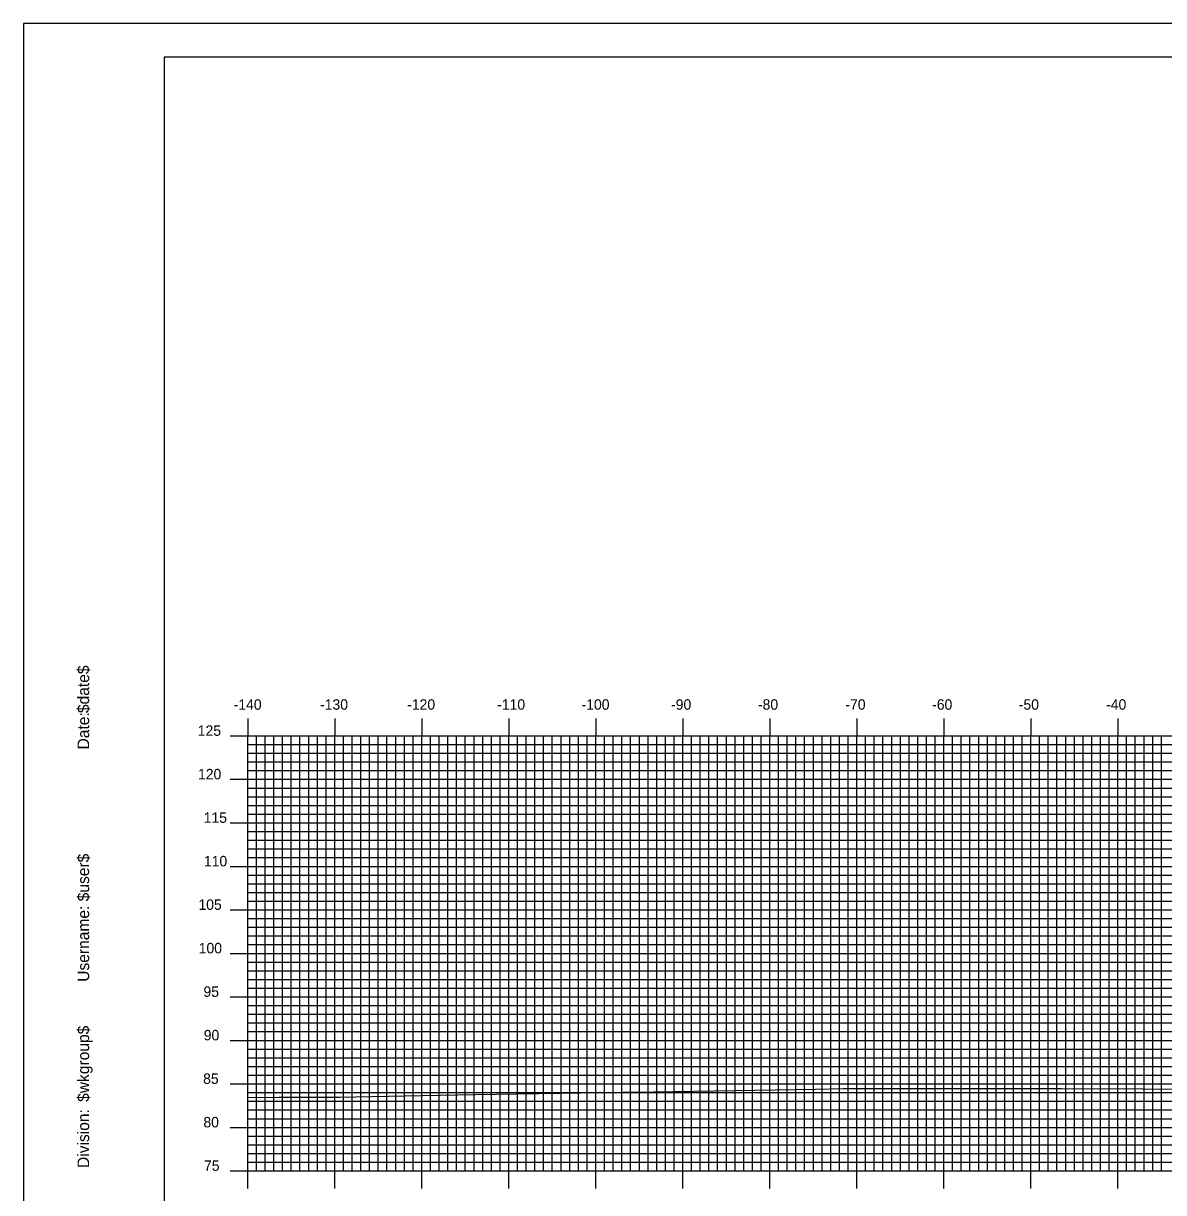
# Model space of a CAD drawing. Extents: x -302 to 42, y -1658 to -1438.
# Drawn here: x -301.7 to -170.6, y -1572.1 to -1437.7 of the extents above; entities that cross this region are included whole.
import ezdxf

# ---------------------------------------------------------------- set-up
doc = ezdxf.new("R2010")
doc.units = 0
for name, color, linetype in [('BORDER', 7, 'Continuous'), ('H_V ANNOTATION', 7, 'Continuous'), ('MAJOR', 7, 'Continuous'), ('MINOR', 7, 'Continuous'), ('PLOT BOUNDARY', 7, 'Continuous'), ('S_Roadway_Centerline', 7, 'Continuous')]:
    doc.layers.add(name, color=color, linetype=linetype)

msp = doc.modelspace()

# ---------------------------------------------------------------- linework, layer by layer
at = {"layer": 'BORDER'}
msp.add_lwpolyline([(-285.49, -1651.6), (34.51, -1651.6), (34.51, -1441.6), (-285.49, -1441.6)], close=True, dxfattribs=at)
at = {"layer": 'MAJOR'}
for p, q in [((-275.89, -1517.6), (-275.89, -1519.6)), ((-265.89, -1517.6), (-265.89, -1519.6)), ((-255.89, -1517.6), (-255.89, -1519.6)), ((-245.89, -1517.6), (-245.89, -1519.6)), ((-235.89, -1517.6), (-235.89, -1519.6)), ((-225.89, -1517.6), (-225.89, -1519.6)), ((-215.89, -1517.6), (-215.89, -1519.6)), ((-205.89, -1517.6), (-205.89, -1519.6)), ((-195.89, -1517.6), (-195.89, -1519.6)), ((-185.89, -1517.6), (-185.89, -1519.6)), ((-175.89, -1517.6), (-175.89, -1519.6)), ((-277.9, -1519.6), (-275.89, -1519.6)), ((-275.89, -1519.6), (4.11, -1519.6)), ((-275.89, -1569.6), (-275.89, -1519.6)), ((-275.89, -1569.6), (-275.89, -1519.6)), ((-275.89, -1519.6), (4.11, -1519.6)), ((-265.89, -1569.6), (-265.89, -1519.6)), ((-255.89, -1569.6), (-255.89, -1519.6)), ((-245.89, -1569.6), (-245.89, -1519.6)), ((-235.89, -1569.6), (-235.89, -1519.6)), ((-225.89, -1569.6), (-225.89, -1519.6)), ((-215.89, -1569.6), (-215.89, -1519.6)), ((-205.89, -1569.6), (-205.89, -1519.6)), ((-195.89, -1569.6), (-195.89, -1519.6)), ((-185.89, -1569.6), (-185.89, -1519.6)), ((-175.89, -1569.6), (-175.89, -1519.6)), ((-277.9, -1524.6), (-275.89, -1524.6)), ((-275.89, -1524.6), (4.11, -1524.6)), ((-277.9, -1529.6), (-275.89, -1529.6)), ((-275.89, -1529.6), (4.11, -1529.6)), ((-277.9, -1534.6), (-275.89, -1534.6)), ((-275.89, -1534.6), (4.11, -1534.6)), ((-277.9, -1539.6), (-275.89, -1539.6)), ((-275.89, -1539.6), (4.11, -1539.6)), ((-277.9, -1544.6), (-275.89, -1544.6)), ((-275.89, -1544.6), (4.11, -1544.6)), ((-277.9, -1549.6), (-275.89, -1549.6)), ((-275.89, -1549.6), (4.11, -1549.6)), ((-277.9, -1554.6), (-275.89, -1554.6)), ((-275.89, -1554.6), (4.11, -1554.6)), ((-277.9, -1559.6), (-275.89, -1559.6)), ((-275.89, -1559.6), (4.11, -1559.6)), ((-277.9, -1564.6), (-275.89, -1564.6)), ((-275.89, -1564.6), (4.11, -1564.6)), ((-277.9, -1569.6), (-275.89, -1569.6)), ((-275.89, -1569.6), (4.11, -1569.6)), ((-275.89, -1569.6), (4.11, -1569.6)), ((-275.89, -1571.61), (-275.89, -1569.6)), ((-265.89, -1571.61), (-265.89, -1569.6)), ((-255.89, -1571.61), (-255.89, -1569.6)), ((-245.89, -1571.61), (-245.89, -1569.6)), ((-235.89, -1571.61), (-235.89, -1569.6)), ((-225.89, -1571.61), (-225.89, -1569.6)), ((-215.89, -1571.61), (-215.89, -1569.6)), ((-205.89, -1571.61), (-205.89, -1569.6)), ((-195.89, -1571.61), (-195.89, -1569.6)), ((-185.89, -1571.61), (-185.89, -1569.6)), ((-175.89, -1571.61), (-175.89, -1569.6))]:
    msp.add_line(p, q, dxfattribs=at)
at = {"layer": 'MINOR'}
for p, q in [((-274.89, -1569.6), (-274.89, -1519.6)), ((-273.89, -1569.6), (-273.89, -1519.6)), ((-272.89, -1569.6), (-272.89, -1519.6)), ((-271.89, -1569.6), (-271.89, -1519.6)), ((-270.89, -1569.6), (-270.89, -1519.6)), ((-269.89, -1569.6), (-269.89, -1519.6)), ((-268.89, -1569.6), (-268.89, -1519.6)), ((-267.89, -1569.6), (-267.89, -1519.6)), ((-266.89, -1569.6), (-266.89, -1519.6)), ((-264.89, -1569.6), (-264.89, -1519.6)), ((-263.89, -1569.6), (-263.89, -1519.6)), ((-262.89, -1569.6), (-262.89, -1519.6)), ((-261.89, -1569.6), (-261.89, -1519.6)), ((-260.89, -1569.6), (-260.89, -1519.6)), ((-259.89, -1569.6), (-259.89, -1519.6)), ((-258.89, -1569.6), (-258.89, -1519.6)), ((-257.89, -1569.6), (-257.89, -1519.6)), ((-256.89, -1569.6), (-256.89, -1519.6)), ((-254.89, -1569.6), (-254.89, -1519.6)), ((-253.89, -1569.6), (-253.89, -1519.6)), ((-252.89, -1569.6), (-252.89, -1519.6)), ((-251.89, -1569.6), (-251.89, -1519.6)), ((-250.89, -1569.6), (-250.89, -1519.6)), ((-249.89, -1569.6), (-249.89, -1519.6)), ((-248.89, -1569.6), (-248.89, -1519.6)), ((-247.89, -1569.6), (-247.89, -1519.6)), ((-246.89, -1569.6), (-246.89, -1519.6)), ((-244.89, -1569.6), (-244.89, -1519.6)), ((-243.89, -1569.6), (-243.89, -1519.6)), ((-242.89, -1569.6), (-242.89, -1519.6)), ((-241.89, -1569.6), (-241.89, -1519.6)), ((-240.89, -1569.6), (-240.89, -1519.6)), ((-239.89, -1569.6), (-239.89, -1519.6)), ((-238.89, -1569.6), (-238.89, -1519.6)), ((-237.89, -1569.6), (-237.89, -1519.6)), ((-236.89, -1569.6), (-236.89, -1519.6)), ((-234.89, -1569.6), (-234.89, -1519.6)), ((-233.89, -1569.6), (-233.89, -1519.6)), ((-232.89, -1569.6), (-232.89, -1519.6)), ((-231.89, -1569.6), (-231.89, -1519.6)), ((-230.89, -1569.6), (-230.89, -1519.6)), ((-229.89, -1569.6), (-229.89, -1519.6)), ((-228.89, -1569.6), (-228.89, -1519.6)), ((-227.89, -1569.6), (-227.89, -1519.6)), ((-226.89, -1569.6), (-226.89, -1519.6)), ((-224.89, -1569.6), (-224.89, -1519.6)), ((-223.89, -1569.6), (-223.89, -1519.6)), ((-222.89, -1569.6), (-222.89, -1519.6)), ((-221.89, -1569.6), (-221.89, -1519.6)), ((-220.89, -1569.6), (-220.89, -1519.6)), ((-219.89, -1569.6), (-219.89, -1519.6)), ((-218.89, -1569.6), (-218.89, -1519.6)), ((-217.89, -1569.6), (-217.89, -1519.6)), ((-216.89, -1569.6), (-216.89, -1519.6)), ((-214.89, -1569.6), (-214.89, -1519.6)), ((-213.89, -1569.6), (-213.89, -1519.6)), ((-212.89, -1569.6), (-212.89, -1519.6)), ((-211.89, -1569.6), (-211.89, -1519.6)), ((-210.89, -1569.6), (-210.89, -1519.6)), ((-209.89, -1569.6), (-209.89, -1519.6)), ((-208.89, -1569.6), (-208.89, -1519.6)), ((-207.89, -1569.6), (-207.89, -1519.6)), ((-206.89, -1569.6), (-206.89, -1519.6)), ((-204.89, -1569.6), (-204.89, -1519.6)), ((-203.89, -1569.6), (-203.89, -1519.6)), ((-202.89, -1569.6), (-202.89, -1519.6)), ((-201.89, -1569.6), (-201.89, -1519.6)), ((-200.89, -1569.6), (-200.89, -1519.6)), ((-199.89, -1569.6), (-199.89, -1519.6)), ((-198.89, -1569.6), (-198.89, -1519.6)), ((-197.89, -1569.6), (-197.89, -1519.6)), ((-196.89, -1569.6), (-196.89, -1519.6)), ((-194.89, -1569.6), (-194.89, -1519.6)), ((-193.89, -1569.6), (-193.89, -1519.6)), ((-192.89, -1569.6), (-192.89, -1519.6)), ((-191.89, -1569.6), (-191.89, -1519.6)), ((-190.89, -1569.6), (-190.89, -1519.6)), ((-189.89, -1569.6), (-189.89, -1519.6)), ((-188.89, -1569.6), (-188.89, -1519.6)), ((-187.89, -1569.6), (-187.89, -1519.6)), ((-186.89, -1569.6), (-186.89, -1519.6)), ((-184.89, -1569.6), (-184.89, -1519.6)), ((-183.89, -1569.6), (-183.89, -1519.6)), ((-182.89, -1569.6), (-182.89, -1519.6)), ((-181.89, -1569.6), (-181.89, -1519.6)), ((-180.89, -1569.6), (-180.89, -1519.6)), ((-179.89, -1569.6), (-179.89, -1519.6)), ((-178.89, -1569.6), (-178.89, -1519.6)), ((-177.89, -1569.6), (-177.89, -1519.6)), ((-176.89, -1569.6), (-176.89, -1519.6)), ((-174.89, -1569.6), (-174.89, -1519.6)), ((-173.89, -1569.6), (-173.89, -1519.6)), ((-172.89, -1569.6), (-172.89, -1519.6)), ((-171.89, -1569.6), (-171.89, -1519.6)), ((-170.89, -1569.6), (-170.89, -1519.6)), ((-275.89, -1520.6), (4.11, -1520.6)), ((-275.89, -1520.6), (-273.89, -1520.6)), ((-275.89, -1521.6), (4.11, -1521.6)), ((-275.89, -1521.6), (-273.89, -1521.6)), ((-275.89, -1522.6), (4.11, -1522.6)), ((-275.89, -1522.6), (-273.89, -1522.6)), ((-275.89, -1523.6), (4.11, -1523.6)), ((-275.89, -1523.6), (-273.89, -1523.6)), ((-275.89, -1525.6), (4.11, -1525.6)), ((-275.89, -1525.6), (-273.89, -1525.6)), ((-275.89, -1526.6), (4.11, -1526.6)), ((-275.89, -1526.6), (-273.89, -1526.6)), ((-275.89, -1527.6), (4.11, -1527.6)), ((-275.89, -1527.6), (-273.89, -1527.6)), ((-275.89, -1528.6), (4.11, -1528.6)), ((-275.89, -1528.6), (-273.89, -1528.6)), ((-275.89, -1530.6), (4.11, -1530.6)), ((-275.89, -1530.6), (-273.89, -1530.6)), ((-275.89, -1531.6), (4.11, -1531.6)), ((-275.89, -1531.6), (-273.89, -1531.6)), ((-275.89, -1532.6), (4.11, -1532.6)), ((-275.89, -1532.6), (-273.89, -1532.6)), ((-275.89, -1533.6), (4.11, -1533.6)), ((-275.89, -1533.6), (-273.89, -1533.6)), ((-275.89, -1535.6), (4.11, -1535.6)), ((-275.89, -1535.6), (-273.89, -1535.6)), ((-275.89, -1536.6), (4.11, -1536.6)), ((-275.89, -1536.6), (-273.89, -1536.6)), ((-275.89, -1537.6), (4.11, -1537.6)), ((-275.89, -1537.6), (-273.89, -1537.6)), ((-275.89, -1538.6), (4.11, -1538.6)), ((-275.89, -1538.6), (-273.89, -1538.6)), ((-275.89, -1540.6), (4.11, -1540.6)), ((-275.89, -1540.6), (-273.89, -1540.6)), ((-275.89, -1541.6), (4.11, -1541.6)), ((-275.89, -1541.6), (-273.89, -1541.6)), ((-275.89, -1542.6), (4.11, -1542.6)), ((-275.89, -1542.6), (-273.89, -1542.6)), ((-275.89, -1543.6), (4.11, -1543.6)), ((-275.89, -1543.6), (-273.89, -1543.6)), ((-275.89, -1545.6), (4.11, -1545.6)), ((-275.89, -1545.6), (-273.89, -1545.6)), ((-275.89, -1546.6), (4.11, -1546.6)), ((-275.89, -1546.6), (-273.89, -1546.6)), ((-275.89, -1547.6), (4.11, -1547.6)), ((-275.89, -1547.6), (-273.89, -1547.6)), ((-275.89, -1548.6), (4.11, -1548.6)), ((-275.89, -1548.6), (-273.89, -1548.6)), ((-275.89, -1550.6), (4.11, -1550.6)), ((-275.89, -1550.6), (-273.89, -1550.6)), ((-275.89, -1551.6), (4.11, -1551.6)), ((-275.89, -1551.6), (-273.89, -1551.6)), ((-275.89, -1552.6), (4.11, -1552.6)), ((-275.89, -1552.6), (-273.89, -1552.6)), ((-275.89, -1553.6), (4.11, -1553.6)), ((-275.89, -1553.6), (-273.89, -1553.6)), ((-275.89, -1555.6), (4.11, -1555.6)), ((-275.89, -1555.6), (-273.89, -1555.6)), ((-275.89, -1556.6), (4.11, -1556.6)), ((-275.89, -1556.6), (-273.89, -1556.6)), ((-275.89, -1557.6), (4.11, -1557.6)), ((-275.89, -1557.6), (-273.89, -1557.6)), ((-275.89, -1558.6), (4.11, -1558.6)), ((-275.89, -1558.6), (-273.89, -1558.6)), ((-275.89, -1560.6), (4.11, -1560.6)), ((-275.89, -1560.6), (-273.89, -1560.6)), ((-275.89, -1561.6), (4.11, -1561.6)), ((-275.89, -1561.6), (-273.89, -1561.6)), ((-275.89, -1562.6), (4.11, -1562.6)), ((-275.89, -1562.6), (-273.89, -1562.6)), ((-275.89, -1563.6), (4.11, -1563.6)), ((-275.89, -1563.6), (-273.89, -1563.6)), ((-275.89, -1565.6), (4.11, -1565.6)), ((-275.89, -1565.6), (-273.89, -1565.6)), ((-275.89, -1566.6), (4.11, -1566.6)), ((-275.89, -1566.6), (-273.89, -1566.6)), ((-275.89, -1567.6), (4.11, -1567.6)), ((-275.89, -1567.6), (-273.89, -1567.6)), ((-275.89, -1568.6), (4.11, -1568.6)), ((-275.89, -1568.6), (-273.89, -1568.6))]:
    msp.add_line(p, q, dxfattribs=at)
at = {"layer": 'PLOT BOUNDARY'}
msp.add_lwpolyline([(-301.68, -1657.72), (38.32, -1657.72), (38.32, -1437.72), (-301.68, -1437.72)], close=True, dxfattribs=at)
at = {"layer": 'S_Roadway_Centerline'}
msp.add_lwpolyline([(-275.89, -1561.17), (-272.33, -1561.12), (-265.36, -1561.12), (-257.83, -1560.98), (-249.72, -1560.84), (-232.73, -1560.54), (-229.27, -1560.5), (-210.64, -1560.2), (-207.48, -1560.14), (-206.85, -1560.14), (-185.89, -1560.15), (-184.26, -1560.14), (-182.37, -1560.12), (-163.66, -1560.2)], dxfattribs=at)

# ---------------------------------------------------------------- texts
at = {"layer": 'BORDER'}
for s, p in [('$date$', (-294.12, -1516.99)), ('Date:', (-294.12, -1521.17)), ('$user$', (-294.12, -1538.62)), ('Username:', (-294.12, -1547.87)), ('$wkgroup$', (-294.12, -1561.67)), ('Division:', (-294.12, -1569.27))]:
    msp.add_text(s, height=1.339, rotation=90, dxfattribs=at).set_placement(p)
at = {"layer": 'H_V ANNOTATION'}
for s, p in [('-140', (-277.51, -1516.6)), ('-130', (-267.58, -1516.6)), ('-120', (-257.57, -1516.6)), ('-110', (-247.23, -1516.6)), ('-100', (-237.53, -1516.6)), ('-90', (-227.24, -1516.6)), ('-80', (-217.26, -1516.6)), ('-70', (-207.21, -1516.6)), ('-60', (-197.24, -1516.6)), ('-50', (-187.28, -1516.6)), ('-40', (-177.24, -1516.6)), ('125', (-281.64, -1519.6)), ('120', (-281.61, -1524.6)), ('115', (-280.96, -1529.6)), ('110', (-280.93, -1534.6)), ('105', (-281.56, -1539.6)), ('100', (-281.53, -1544.6)), ('95', (-280.98, -1549.6)), ('90', (-280.95, -1554.6)), ('85', (-281.02, -1559.6)), ('80', (-280.99, -1564.6)), ('75', (-280.92, -1569.6))]:
    msp.add_text(s, height=1.2, dxfattribs=at).set_placement(p)
at = {"layer": 'MAJOR'}
msp.add_text('-', height=0.012, dxfattribs=at).set_placement((-275.9, -1569.6))

doc.saveas('drawing.dxf')
